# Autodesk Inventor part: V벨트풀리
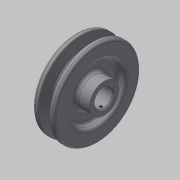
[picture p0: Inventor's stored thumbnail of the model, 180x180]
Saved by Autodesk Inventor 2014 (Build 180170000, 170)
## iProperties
Created: 2015-11
Part Number: V벨트풀리
Material: 강철, 탄소
Document SubType Name: Modeling
Designer: mduedu
Density: 1 g/cm^3
Appearance: 기본값
Author: mduedu
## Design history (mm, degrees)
sketch "스케치1"
  geometry: L1 (-9.5, 0)-(9.5, 0); L2 (0, 0)-(0, 37.7); L3 (-4.825, 37.7)-(-9.5, 37.7); L4 (-9.5, 37.7)-(-9.5, 0); L5 (0, 28.7)-(-2.074, 28.7); L6 (-2.074, 28.7)-(-4.825, 37.7); L7 (4.825, 37.7)-(9.5, 37.7); L8 (9.5, 37.7)-(9.5, 0); L9 (0, 28.7)-(2.074, 28.7); L10 (2.074, 28.7)-(4.825, 37.7); L11 (-9.5, 35)-(9.5, 35); 3 further points
  constraints: 22 end point, 7 point on line, 4 perpendicular, 3 symmetric about line, 1 coincident, 1 horizontal, 1 horizontal alignment, 1 midpoint, 1 vertical
  dimensions: "d0" = 19 distance of L1.start L1.end; "d2" = 75.4 diameter of L2.end L1 (derived); "d3" = 34 deg angle of L10 L6; "d4" = 6.3 distance between parallel lines of L11 L9; "d5" = 2.7 distance between parallel lines of L7 L11; "d6" = 8 distance of point (4, 35) point (-4, 35); "d7" = 70 diameter of L11 L1
revolve "회전1" sketch "스케치1" stored, may be unused: angle "d8" = 90 deg
sketch "스케치2"
  geometry: C1 r 24 at (0, 0); C2 r 13 at (0, 0); 1 further point
  constraints: 2 centre point, 2 coincident
  dimensions: "d9" = 48 diameter of C1; "d10" = 26 diameter of C2
extrude "돌출1" cut sketch "스케치2" distance "d11" = 6; taper "d12" = 0 deg
extrude "돌출3" join sketch "스케치2" distance "d37" = 6; taper "d38" = 0 deg
fillet "모깎기1" dims "d13" = 3
fillet "모깎기2" dims "d14" = 3
fillet "모깎기3" dims "d15" = 1, "d16" = 0.5, "d17" = 2
hole "구멍1" diameter "d20" = 16; stored, may be unused: countersink angle "d24" = 90 deg, drill point angle "d26" = 118 deg; dims "d21" = 6, "d22" = 4, "d23" = 2, "d25" = 8, "d53" = 10, "d54" = 10
sketch "스케치3"
  geometry: L1 (-2.5, 0)-(2.5, 0); L2 (2.5, 0)-(2.5, 10.3); L3 (2.5, 10.3)-(-2.5, 10.3); L4 (-2.5, 10.3)-(-2.5, 0); 2 further points
  constraints: 8 end point, 2 parallel, 1 coincident, 1 horizontal, 1 midpoint, 1 perpendicular
  dimensions: "d27" = 5 distance of L2.end L3.end; "d29" = 10.3 distance of L3.end L1.start
extrude "돌출2" cut sketch "스케치3" stored distance "d30" = 6; taper "d31" = 0 deg
chamfer "모따기1" distance "d32" = 1; stored, may be unused: second distance "d33" = 2, angle "d34" = 45 deg
node "작업 평면1"
sketch "스케치4"
  geometry: L1 (19, -27)-(19, 27) reference; 2 further points
  constraints: 1 horizontal alignment
  dimensions: "d52" = 22 distance from line of L1 point (-3, 0)
hole "구멍2" sketch "스케치4" at (-3, 0) diameter "d42" = 2.459; stored, may be unused: countersink angle "d46" = 90 deg, drill point angle "d48" = 118 deg; dims "d43" = 6, "d44" = 4, "d45" = 2, "d47" = 8
chamfer "모따기3" distance "d58" = 1; stored, may be unused: second distance "d59" = 2, angle "d60" = 45 deg
node "솔리드1"
mirror "대칭1"
